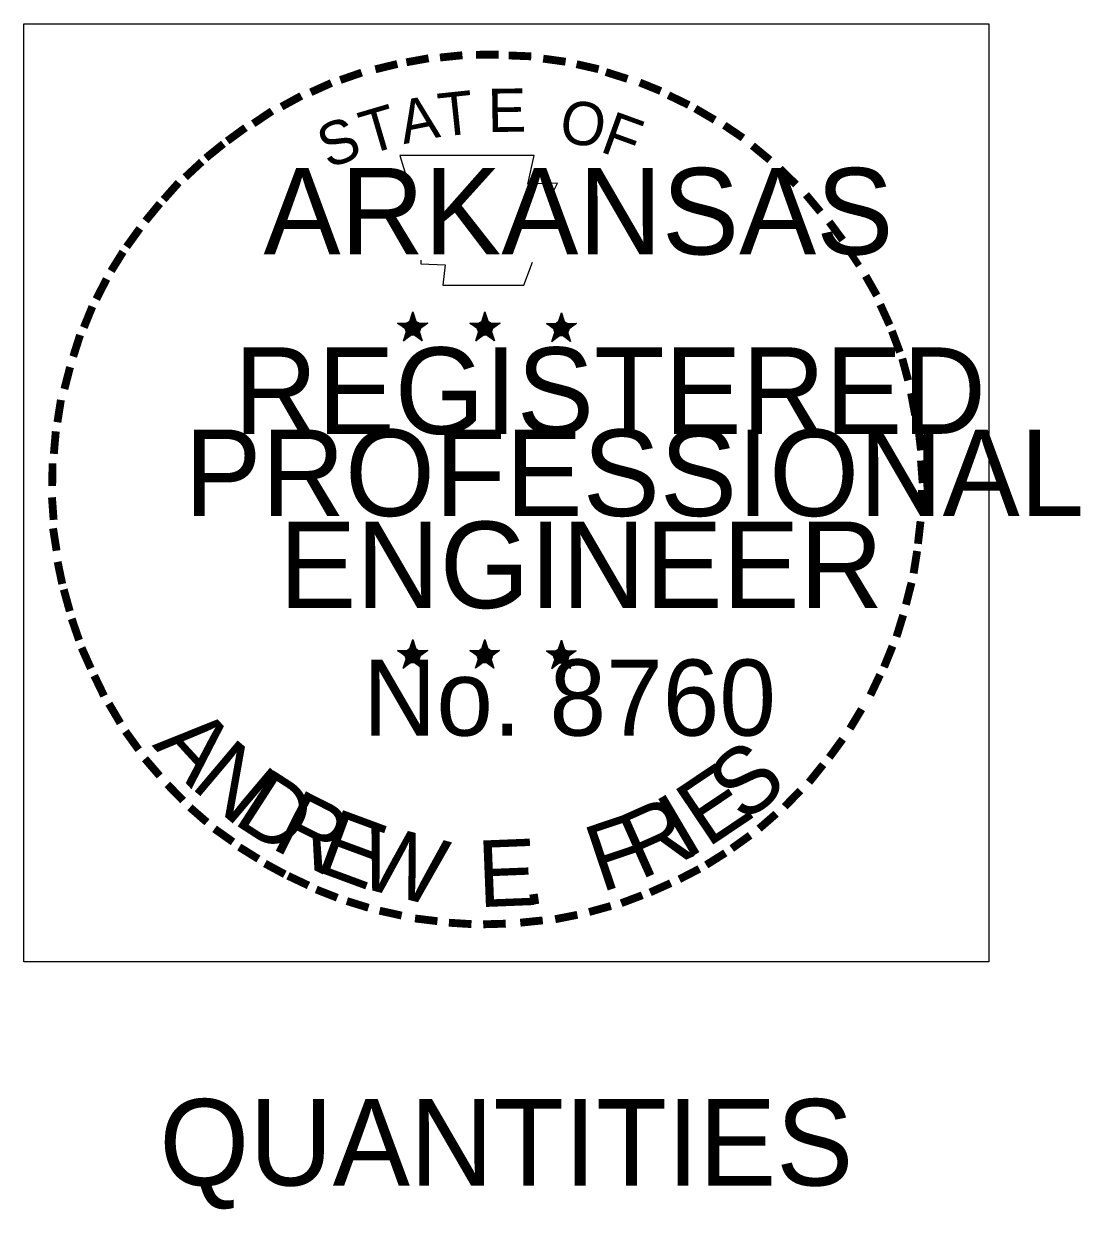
# Model space of a CAD drawing. Extents: x 1226561 to 1228164, y 151309 to 152305.
# Drawn here: x 1228011.2 to 1228163.9, y 151309.4 to 151480.8 of the extents above; entities that cross this region are included whole.
import ezdxf

# ---------------------------------------------------------------- set-up
doc = ezdxf.new("R2010")
doc.units = 0
for name, color, linetype in [('R_Border Notes', 7, 'Continuous'), ('R_Border PE', 7, 'Continuous'), ('R_Border Prem', 7, 'Continuous')]:
    doc.layers.add(name, color=color, linetype=linetype)

msp = doc.modelspace()

# ---------------------------------------------------------------- linework, layer by layer
at = {"layer": 'R_Border PE'}
for p, q in [((1228067.4, 151439.11), (1228067.09, 151437.55)), ((1228067.4, 151439.11), (1228067.15, 151437.49)), ((1228067.4, 151439.11), (1228067.34, 151437.55)), ((1228067.4, 151436.8), (1228067.4, 151439.11)), ((1228067.4, 151439.11), (1228067.84, 151437.49)), ((1228067.4, 151439.11), (1228067.72, 151437.55)), ((1228067.4, 151439.11), (1228067.59, 151437.55)), ((1228077.84, 151439.11), (1228077.53, 151437.55)), ((1228077.84, 151439.11), (1228077.59, 151437.49)), ((1228077.84, 151439.11), (1228077.72, 151437.55)), ((1228077.84, 151436.8), (1228077.84, 151439.11)), ((1228077.84, 151439.11), (1228078.28, 151437.49)), ((1228077.84, 151439.11), (1228078.15, 151437.55)), ((1228077.84, 151439.11), (1228077.97, 151437.55)), ((1228088.9, 151438.99), (1228088.53, 151437.49)), ((1228088.9, 151438.99), (1228088.65, 151437.43)), ((1228088.9, 151438.99), (1228088.78, 151437.43)), ((1228088.9, 151436.74), (1228088.9, 151438.99)), ((1228088.9, 151438.99), (1228089.34, 151437.43)), ((1228088.9, 151438.99), (1228089.22, 151437.43)), ((1228088.9, 151438.99), (1228089.03, 151437.49)), ((1228065.22, 151437.49), (1228067.4, 151436.8)), ((1228065.22, 151437.49), (1228066.84, 151437.36)), ((1228065.22, 151437.49), (1228066.84, 151437.24)), ((1228065.22, 151437.49), (1228066.78, 151437.11)), ((1228065.22, 151437.49), (1228066.78, 151436.86)), ((1228065.22, 151437.49), (1228066.72, 151436.74)), ((1228065.22, 151437.49), (1228066.72, 151436.61)), ((1228066.09, 151434.93), (1228067.4, 151436.8)), ((1228066.09, 151434.93), (1228066.78, 151436.68)), ((1228066.09, 151434.93), (1228066.84, 151436.49)), ((1228066.09, 151434.93), (1228066.97, 151436.43)), ((1228066.09, 151434.93), (1228067.4, 151436.3)), ((1228069.59, 151437.49), (1228067.4, 151436.8)), ((1228068.78, 151434.93), (1228067.4, 151436.8)), ((1228068.78, 151434.93), (1228067.4, 151436.3)), ((1228069.59, 151437.49), (1228067.65, 151437.36)), ((1228069.59, 151437.49), (1228067.78, 151437.18)), ((1228069.59, 151437.49), (1228067.78, 151437.05)), ((1228068.78, 151434.93), (1228067.84, 151436.49)), ((1228068.78, 151434.93), (1228067.9, 151436.74)), ((1228068.78, 151434.93), (1228068.03, 151436.8)), ((1228069.59, 151437.49), (1228068.22, 151436.93)), ((1228069.59, 151437.49), (1228068.34, 151436.86)), ((1228069.59, 151437.49), (1228068.4, 151436.8)), ((1228075.65, 151437.49), (1228077.84, 151436.8)), ((1228075.65, 151437.49), (1228077.28, 151437.36)), ((1228075.65, 151437.49), (1228077.28, 151437.24)), ((1228075.65, 151437.49), (1228077.22, 151437.11)), ((1228075.65, 151437.49), (1228077.15, 151436.86)), ((1228075.65, 151437.49), (1228077.15, 151436.74)), ((1228075.65, 151437.49), (1228077.15, 151436.61)), ((1228076.53, 151434.93), (1228077.84, 151436.8)), ((1228076.53, 151434.93), (1228077.22, 151436.68)), ((1228076.53, 151434.93), (1228077.28, 151436.49)), ((1228076.53, 151434.93), (1228077.4, 151436.43)), ((1228076.53, 151434.93), (1228077.84, 151436.3)), ((1228080.03, 151437.49), (1228077.84, 151436.8)), ((1228079.22, 151434.93), (1228077.84, 151436.8)), ((1228079.22, 151434.93), (1228077.84, 151436.3)), ((1228080.03, 151437.49), (1228078.09, 151437.36)), ((1228080.03, 151437.49), (1228078.22, 151437.18)), ((1228080.03, 151437.49), (1228078.22, 151437.05)), ((1228079.22, 151434.93), (1228078.28, 151436.49)), ((1228079.22, 151434.93), (1228078.34, 151436.74)), ((1228079.22, 151434.93), (1228078.47, 151436.8)), ((1228080.03, 151437.49), (1228078.65, 151436.93)), ((1228080.03, 151437.49), (1228078.78, 151436.86)), ((1228080.03, 151437.49), (1228078.84, 151436.8)), ((1228086.72, 151437.43), (1228088.9, 151436.74)), ((1228086.72, 151437.43), (1228088.34, 151437.24)), ((1228086.72, 151437.43), (1228088.28, 151437.11)), ((1228086.72, 151437.43), (1228088.28, 151437.05)), ((1228086.72, 151437.43), (1228088.22, 151436.8)), ((1228086.72, 151437.43), (1228088.22, 151436.68)), ((1228086.72, 151437.43), (1228088.22, 151436.55)), ((1228087.53, 151434.86), (1228088.9, 151436.74)), ((1228087.53, 151434.86), (1228088.28, 151436.61)), ((1228087.53, 151434.86), (1228088.34, 151436.43)), ((1228087.53, 151434.86), (1228088.47, 151436.36)), ((1228091.09, 151437.43), (1228088.9, 151436.74)), ((1228090.22, 151434.86), (1228088.9, 151436.74)), ((1228091.09, 151437.43), (1228089.15, 151437.3)), ((1228091.09, 151437.43), (1228089.28, 151437.11)), ((1228091.09, 151437.43), (1228089.28, 151436.99)), ((1228090.22, 151434.86), (1228089.34, 151436.43)), ((1228090.22, 151434.86), (1228089.4, 151436.68)), ((1228090.22, 151434.86), (1228089.53, 151436.68)), ((1228091.09, 151437.43), (1228089.72, 151436.86)), ((1228091.09, 151437.43), (1228089.78, 151436.8)), ((1228091.09, 151437.43), (1228089.9, 151436.74)), ((1228066.09, 151434.93), (1228067.15, 151436.24)), ((1228066.09, 151434.93), (1228067.47, 151436.11)), ((1228068.78, 151434.93), (1228067.4, 151436.11)), ((1228068.78, 151434.93), (1228067.65, 151436.24)), ((1228076.53, 151434.93), (1228077.59, 151436.24)), ((1228076.53, 151434.93), (1228077.9, 151436.11)), ((1228079.22, 151434.93), (1228077.84, 151436.11)), ((1228079.22, 151434.93), (1228078.09, 151436.24)), ((1228087.53, 151434.86), (1228088.9, 151436.24)), ((1228087.53, 151434.86), (1228088.65, 151436.18)), ((1228087.53, 151434.86), (1228088.97, 151436.05)), ((1228090.22, 151434.86), (1228088.9, 151436.24)), ((1228090.22, 151434.86), (1228088.9, 151436.05)), ((1228090.22, 151434.86), (1228089.15, 151436.18)), ((1228067.4, 151391.74), (1228067.03, 151390.24)), ((1228067.4, 151391.74), (1228067.15, 151390.18)), ((1228067.4, 151391.74), (1228067.28, 151390.18)), ((1228067.4, 151389.49), (1228067.4, 151391.74)), ((1228067.4, 151391.74), (1228067.84, 151390.18)), ((1228067.4, 151391.74), (1228067.72, 151390.18)), ((1228067.4, 151391.74), (1228067.53, 151390.18)), ((1228077.84, 151391.74), (1228077.47, 151390.24)), ((1228077.84, 151391.74), (1228077.59, 151390.18)), ((1228077.84, 151391.74), (1228077.72, 151390.18)), ((1228077.84, 151389.49), (1228077.84, 151391.74)), ((1228077.84, 151391.74), (1228078.22, 151390.18)), ((1228077.84, 151391.74), (1228078.15, 151390.18)), ((1228077.84, 151391.74), (1228077.97, 151390.18)), ((1228065.22, 151390.18), (1228067.4, 151389.49)), ((1228065.22, 151390.18), (1228066.84, 151389.99)), ((1228065.22, 151390.18), (1228066.78, 151389.86)), ((1228065.22, 151390.18), (1228066.78, 151389.8)), ((1228065.22, 151390.18), (1228066.72, 151389.55)), ((1228065.22, 151390.18), (1228066.72, 151389.43)), ((1228065.22, 151390.18), (1228066.72, 151389.3)), ((1228069.59, 151390.18), (1228067.4, 151389.49)), ((1228069.59, 151390.18), (1228067.65, 151390.05)), ((1228069.59, 151390.18), (1228067.78, 151389.86)), ((1228069.59, 151390.18), (1228067.78, 151389.74)), ((1228069.59, 151390.18), (1228068.15, 151389.61)), ((1228069.59, 151390.18), (1228068.28, 151389.55)), ((1228069.59, 151390.18), (1228068.4, 151389.43)), ((1228075.65, 151390.18), (1228077.84, 151389.49)), ((1228075.65, 151390.18), (1228077.22, 151389.99)), ((1228075.65, 151390.18), (1228077.22, 151389.86)), ((1228075.65, 151390.18), (1228077.22, 151389.8)), ((1228075.65, 151390.18), (1228077.15, 151389.55)), ((1228075.65, 151390.18), (1228077.15, 151389.43)), ((1228075.65, 151390.18), (1228077.15, 151389.3)), ((1228079.97, 151390.18), (1228077.84, 151389.49)), ((1228079.97, 151390.18), (1228078.09, 151390.05)), ((1228079.97, 151390.18), (1228078.22, 151389.86)), ((1228079.97, 151390.18), (1228078.22, 151389.74)), ((1228079.97, 151390.18), (1228078.59, 151389.61)), ((1228079.97, 151390.18), (1228078.72, 151389.55)), ((1228079.97, 151390.18), (1228078.84, 151389.43)), ((1228086.72, 151390.11), (1228088.9, 151389.43)), ((1228086.72, 151390.11), (1228088.28, 151389.93)), ((1228086.72, 151390.11), (1228088.28, 151389.8)), ((1228086.72, 151390.11), (1228088.22, 151389.68)), ((1228086.72, 151390.11), (1228088.22, 151389.49)), ((1228086.72, 151390.11), (1228088.15, 151389.3)), ((1228086.72, 151390.11), (1228088.15, 151389.18)), ((1228088.9, 151391.68), (1228088.53, 151390.11)), ((1228088.9, 151391.68), (1228088.65, 151390.11)), ((1228088.9, 151391.68), (1228088.78, 151390.11)), ((1228088.9, 151389.43), (1228088.9, 151391.68)), ((1228088.9, 151391.68), (1228089.28, 151390.11)), ((1228088.9, 151391.68), (1228089.22, 151390.11)), ((1228088.9, 151391.68), (1228089.03, 151390.11)), ((1228091.03, 151390.11), (1228088.9, 151389.43)), ((1228091.03, 151390.11), (1228089.15, 151389.99)), ((1228091.03, 151390.11), (1228089.28, 151389.8)), ((1228091.03, 151390.11), (1228089.28, 151389.68)), ((1228091.03, 151390.11), (1228089.65, 151389.55)), ((1228091.03, 151390.11), (1228089.78, 151389.43)), ((1228091.03, 151390.11), (1228089.84, 151389.36)), ((1228066.03, 151387.61), (1228067.4, 151389.49)), ((1228066.03, 151387.61), (1228066.78, 151389.36)), ((1228066.03, 151387.61), (1228066.84, 151389.11)), ((1228066.03, 151387.61), (1228066.97, 151389.05)), ((1228066.03, 151387.61), (1228067.4, 151388.99)), ((1228066.03, 151387.61), (1228067.15, 151388.93)), ((1228066.03, 151387.61), (1228067.4, 151388.8)), ((1228068.72, 151387.61), (1228067.34, 151388.8)), ((1228068.72, 151387.61), (1228067.4, 151389.49)), ((1228068.72, 151387.61), (1228067.4, 151388.93)), ((1228068.72, 151387.61), (1228067.59, 151388.93)), ((1228068.72, 151387.61), (1228067.84, 151389.43)), ((1228068.72, 151387.61), (1228067.84, 151389.18)), ((1228068.72, 151387.61), (1228068.03, 151389.43)), ((1228076.47, 151387.61), (1228077.84, 151389.49)), ((1228076.47, 151387.61), (1228077.22, 151389.36)), ((1228076.47, 151387.61), (1228077.28, 151389.11)), ((1228076.47, 151387.61), (1228077.4, 151389.05)), ((1228076.47, 151387.61), (1228077.84, 151388.99)), ((1228076.47, 151387.61), (1228077.59, 151388.93)), ((1228076.47, 151387.61), (1228077.84, 151388.8)), ((1228079.15, 151387.61), (1228077.78, 151388.8)), ((1228079.15, 151387.61), (1228077.84, 151389.49)), ((1228079.15, 151387.61), (1228077.84, 151388.93)), ((1228079.15, 151387.61), (1228078.03, 151388.93)), ((1228079.15, 151387.61), (1228078.28, 151389.43)), ((1228079.15, 151387.61), (1228078.28, 151389.18)), ((1228079.15, 151387.61), (1228078.47, 151389.43)), ((1228087.53, 151387.55), (1228088.9, 151389.43)), ((1228087.53, 151387.55), (1228088.22, 151389.3)), ((1228087.53, 151387.55), (1228088.28, 151389.05)), ((1228087.53, 151387.55), (1228088.47, 151388.99)), ((1228087.53, 151387.55), (1228088.65, 151388.86)), ((1228087.53, 151387.55), (1228088.84, 151388.86)), ((1228087.53, 151387.55), (1228088.9, 151388.74)), ((1228090.22, 151387.55), (1228088.84, 151388.86)), ((1228090.22, 151387.55), (1228088.84, 151388.68)), ((1228090.22, 151387.55), (1228088.9, 151389.43)), ((1228090.22, 151387.55), (1228089.09, 151388.86)), ((1228090.22, 151387.55), (1228089.28, 151389.05)), ((1228090.22, 151387.55), (1228089.34, 151389.36)), ((1228090.22, 151387.55), (1228089.47, 151389.36))]:
    msp.add_line(p, q, dxfattribs=at)
for points in [[(1228065.53, 151461.74), (1228067.15, 151456.55)], [(1228087.47, 151455.99), (1228088.34, 151457.74), (1228084.03, 151457.61), (1228084.97, 151461.74), (1228065.53, 151461.74)], [(1228068.59, 151446.61), (1228068.59, 151446.05), (1228072.09, 151445.93), (1228071.78, 151442.99), (1228083.47, 151442.99), (1228084.72, 151446.3)], [(1228067.4, 151439.11), (1228068.78, 151434.93), (1228065.22, 151437.49), (1228069.59, 151437.49), (1228066.09, 151434.93), (1228067.4, 151439.11)], [(1228077.84, 151439.11), (1228079.22, 151434.93), (1228075.65, 151437.49), (1228080.03, 151437.49), (1228076.53, 151434.93), (1228077.84, 151439.11)], [(1228088.9, 151438.99), (1228090.22, 151434.86), (1228086.72, 151437.43), (1228091.09, 151437.43), (1228087.53, 151434.86), (1228088.9, 151438.99)], [(1228067.4, 151391.74), (1228068.72, 151387.61), (1228065.22, 151390.18), (1228069.59, 151390.18), (1228066.03, 151387.61), (1228067.4, 151391.74)], [(1228077.84, 151391.74), (1228079.15, 151387.61), (1228075.65, 151390.18), (1228079.97, 151390.18), (1228076.47, 151387.61), (1228077.84, 151391.74)], [(1228088.9, 151391.68), (1228090.22, 151387.55), (1228086.72, 151390.11), (1228091.03, 151390.11), (1228087.53, 151387.55), (1228088.9, 151391.68)]]:
    msp.add_lwpolyline(points, dxfattribs=at)
for centre, radius in [((1228067.42, 151436.8), 1.08), ((1228067.42, 151436.8), 0.975), ((1228067.42, 151436.8), 0.904), ((1228067.42, 151436.8), 0.83), ((1228067.42, 151436.8), 0.723), ((1228067.42, 151436.8), 0.672), ((1228067.42, 151436.8), 0.619), ((1228067.42, 151436.8), 0.533), ((1228067.42, 151436.8), 0.467), ((1228067.42, 151436.8), 0.388), ((1228067.42, 151436.8), 0.31), ((1228067.42, 151436.8), 0.231), ((1228067.42, 151436.8), 0.185), ((1228067.42, 151436.8), 0.0901), ((1228077.85, 151436.8), 1.08), ((1228077.85, 151436.8), 0.975), ((1228077.85, 151436.8), 0.904), ((1228077.85, 151436.8), 0.83), ((1228077.85, 151436.8), 0.723), ((1228077.85, 151436.8), 0.672), ((1228077.85, 151436.8), 0.619), ((1228077.85, 151436.8), 0.533), ((1228077.85, 151436.8), 0.467), ((1228077.85, 151436.8), 0.388), ((1228077.85, 151436.8), 0.31), ((1228077.85, 151436.8), 0.231), ((1228077.85, 151436.8), 0.185), ((1228077.85, 151436.8), 0.0901), ((1228088.9, 151436.72), 1.08), ((1228088.9, 151436.72), 0.975), ((1228088.9, 151436.72), 0.904), ((1228088.9, 151436.72), 0.83), ((1228088.9, 151436.72), 0.723), ((1228088.9, 151436.72), 0.672), ((1228088.9, 151436.72), 0.619), ((1228088.9, 151436.72), 0.533), ((1228088.9, 151436.72), 0.467), ((1228088.9, 151436.72), 0.388), ((1228088.9, 151436.72), 0.31), ((1228088.9, 151436.72), 0.231), ((1228088.9, 151436.72), 0.185), ((1228088.9, 151436.72), 0.0901), ((1228067.4, 151389.46), 1.08), ((1228067.4, 151389.46), 0.975), ((1228067.4, 151389.46), 0.904), ((1228067.4, 151389.46), 0.83), ((1228067.4, 151389.46), 0.723), ((1228067.4, 151389.46), 0.672), ((1228067.4, 151389.46), 0.619), ((1228067.4, 151389.46), 0.533), ((1228077.83, 151389.46), 1.08), ((1228077.83, 151389.46), 0.975), ((1228077.83, 151389.46), 0.904), ((1228077.83, 151389.46), 0.83), ((1228077.83, 151389.46), 0.723), ((1228077.83, 151389.46), 0.672), ((1228077.83, 151389.46), 0.619), ((1228077.83, 151389.46), 0.533), ((1228088.87, 151389.39), 1.08), ((1228088.87, 151389.39), 0.975), ((1228088.87, 151389.39), 0.904), ((1228088.87, 151389.39), 0.83), ((1228088.87, 151389.39), 0.723), ((1228088.87, 151389.39), 0.672), ((1228088.87, 151389.39), 0.619), ((1228067.4, 151389.46), 0.467), ((1228067.4, 151389.46), 0.388), ((1228067.4, 151389.46), 0.31), ((1228067.4, 151389.46), 0.231), ((1228067.4, 151389.46), 0.185), ((1228067.4, 151389.46), 0.0901), ((1228077.83, 151389.46), 0.467), ((1228077.83, 151389.46), 0.388), ((1228077.83, 151389.46), 0.31), ((1228077.83, 151389.46), 0.231), ((1228077.83, 151389.46), 0.185), ((1228077.83, 151389.46), 0.0901), ((1228088.87, 151389.39), 0.533), ((1228088.87, 151389.39), 0.467), ((1228088.87, 151389.39), 0.388), ((1228088.87, 151389.39), 0.31), ((1228088.87, 151389.39), 0.231), ((1228088.87, 151389.39), 0.185), ((1228088.87, 151389.39), 0.0901)]:
    msp.add_circle(centre, radius, dxfattribs=at)
at = {"layer": 'R_Border Prem'}
msp.add_lwpolyline([(1228011.18, 151480.78), (1228150.68, 151480.78), (1228150.68, 151345.16), (1228011.18, 151345.16)], close=True, dxfattribs=at)

# ---------------------------------------------------------------- texts
at = {"layer": 'R_Border Notes'}
msp.add_text('QUANTITIES', height=12.5, dxfattribs=at).set_placement((1228030.78, 151312.82))
at = {"layer": 'R_Border PE'}
for s, height, rotation, p in [('-', 10, 10.2193, (1228066.59, 151471.3)), ('-', 10, 5.8968, (1228071.15, 151471.99)), ('-', 10, 0.1862, (1228075.97, 151472.43)), ('-', 10, 357.743, (1228080.53, 151472.36)), ('-', 10, 352.1617, (1228085.15, 151471.99)), ('-', 10, 19.1761, (1228057.65, 151468.8)), ('-', 10, 13.6302, (1228062.34, 151470.3)), ('-', 10, 347.2049, (1228089.65, 151471.3)), ('-', 10, 342.3362, (1228093.59, 151470.3)), ('-', 10, 24.3072, (1228053.72, 151467.11)), ('-', 10, 337.8551, (1228098.22, 151468.93)), ('-', 10, 28.7918, (1228049.78, 151465.11)), ('T', 6.25, 6.0228, (1228071.4, 151464.43)), ('E', 6.25, 0.8323, (1228078.28, 151465.11)), ('-', 10, 334.1211, (1228102.15, 151467.24)), ('T', 6.25, 16.4036, (1228060.9, 151461.8)), ('A', 6.25, 11.2132, (1228066.09, 151463.36)), ('O', 6.25, 350.4515, (1228088.34, 151463.8)), ('-', 10, 329.6409, (1228105.78, 151465.49)), ('-', 10, 34.0636, (1228046.03, 151462.8)), ('F', 6.25, 340.0707, (1228094.28, 151462.36)), ('-', 10, 36.2317, (1228042.4, 151460.36)), ('S', 6.25, 21.594, (1228055.22, 151459.74)), ('-', 10, 325.8627, (1228109.78, 151463.24)), ('-', 10, 38.9507, (1228039.47, 151457.99)), ('-', 10, 320.5297, (1228113.59, 151460.55)), ('-', 10, 42.9622, (1228036.72, 151455.36)), ('-', 10, 315.5786, (1228117.34, 151457.49)), ('-', 10, 48.423, (1228033.9, 151452.36)), ('-', 10, 50.6142, (1228031.4, 151449.36)), ('-', 10, 309.8797, (1228120.9, 151454.05)), ('-', 10, 306.6522, (1228124.15, 151450.3)), ('-', 10, 54.2325, (1228028.84, 151445.8)), ('-', 8.75, 303.6753, (1228127.22, 151446.74)), ('-', 10, 58.0706, (1228026.78, 151442.49)), ('-', 10, 62.8713, (1228024.84, 151438.68)), ('-', 10, 299.6684, (1228129.22, 151442.93)), ('-', 10, 67.7743, (1228023.22, 151434.86)), ('-', 10, 294.6628, (1228131.22, 151439.11)), ('-', 10, 290.5728, (1228132.84, 151435.55)), ('-', 10, 72.3945, (1228021.84, 151430.93)), ('-', 10, 75.461, (1228020.65, 151426.43)), ('-', 10, 285.1233, (1228134.28, 151431.93)), ('-', 10, 81.2013, (1228019.78, 151421.99)), ('-', 10, 280.5493, (1228135.53, 151427.24)), ('-', 10, 85.1863, (1228019.34, 151417.68)), ('-', 10, 276.5962, (1228136.59, 151422.49)), ('-', 10, 274.3301, (1228136.97, 151417.93)), ('-', 10, 89.0622, (1228019.15, 151413.3)), ('-', 10, 94.1959, (1228019.4, 151408.74)), ('-', 10, 269.9407, (1228137.15, 151413.99)), ('-', 10, 263.5172, (1228137.03, 151409.86)), ('-', 10, 98.9479, (1228019.84, 151404.61)), ('-', 10, 260.9953, (1228136.59, 151405.74)), ('-', 10, 101.7149, (1228020.65, 151399.99)), ('-', 10, 105.4578, (1228021.72, 151396.3)), ('-', 10, 255.7626, (1228135.9, 151401.49)), ('-', 10, 252.8681, (1228134.78, 151396.99)), ('-', 10, 109.0874, (1228023.03, 151392.36)), ('-', 10, 114.0643, (1228024.65, 151388.61)), ('-', 10, 247.8887, (1228133.4, 151392.8)), ('-', 10, 115.7289, (1228026.53, 151384.74)), ('-', 10, 244.6197, (1228131.72, 151388.86)), ('-', 10, 120.4471, (1228028.78, 151381.11)), ('-', 10, 239.0712, (1228129.28, 151384.18)), ('A', 9.62, 312.4727, (1228029.65, 151376.42)), ('-', 10, 125.8934, (1228031.28, 151377.61)), ('N', 9.62, 319.8362, (1228035.09, 151370.49)), ('S', 9.62, 39.723, (1228115.32, 151365.02)), ('-', 10, 233.8452, (1228126.78, 151380.11)), ('-', 10, 130.7181, (1228034.15, 151374.11)), ('E', 9.62, 33.8878, (1228109.98, 151361.54)), ('-', 10, 231.2538, (1228124.09, 151376.55)), ('-', 10, 134.2238, (1228037.4, 151370.74)), ('D', 9.62, 327.1996, (1228041.23, 151365.3)), ('R', 9.62, 333.1738, (1228046.68, 151361.7)), ('-', 10, 225.7653, (1228121.09, 151373.05)), ('-', 10, 138.9338, (1228040.65, 151367.86)), ('R', 9.62, 24.0235, (1228100.24, 151356.94)), ('I', 9.62, 30.5534, (1228106.78, 151359.8)), ('E', 9.62, 339.7037, (1228053.02, 151358.43)), ('F', 9.62, 18.6051, (1228094.6, 151355.14)), ('-', 10, 221.0851, (1228117.84, 151369.86)), ('-', 10, 144.6463, (1228044.15, 151365.3)), ('W', 9.62, 345.5389, (1228058.97, 151356.14)), ('E', 9.62, 2.2804, (1228076.94, 151353.05)), ('-', 10, 215.7363, (1228114.4, 151366.93)), ('-', 10, 148.0898, (1228047.65, 151362.99)), ('-', 10, 212.2491, (1228111.03, 151364.49)), ('-', 10, 151.5704, (1228051.28, 151360.93)), ('-', 10, 154.6002, (1228054.53, 151359.43)), ('-', 10, 207.3568, (1228107.59, 151362.3)), ('-', 10, 158.5612, (1228058.47, 151357.8)), ('-', 10, 204.2516, (1228103.65, 151360.3)), ('-', 10, 162.7983, (1228062.72, 151356.49)), ('.', 9.62, 8.1156, (1228083.31, 151353.22)), ('-', 10, 200.7184, (1228099.78, 151358.61)), ('-', 10, 167.5555, (1228067.22, 151355.49)), ('-', 10, 191.2858, (1228091.03, 151355.86)), ('-', 10, 195.4743, (1228095.59, 151357.11)), ('-', 10, 173.1155, (1228072.03, 151354.8)), ('-', 10, 176.5183, (1228076.72, 151354.43)), ('-', 10, 181.5918, (1228081.34, 151354.55)), ('-', 10, 185.8167, (1228086.4, 151355.05))]:
    msp.add_text(s, height=height, rotation=rotation, dxfattribs=at).set_placement(p)
for s, height, p in [('ARKANSAS', 12.5, (1228045.84, 151447.43)), ('REGISTERED', 12.5, (1228041.59, 151421.49)), ('PROFESSIONAL', 12.4999, (1228034.4, 151409.61)), ('ENGINEER', 12.5, (1228048.09, 151396.3)), ('No. 8760', 11, (1228060.2, 151377.86))]:
    msp.add_text(s, height=height, dxfattribs=at).set_placement(p)

doc.saveas('drawing.dxf')
